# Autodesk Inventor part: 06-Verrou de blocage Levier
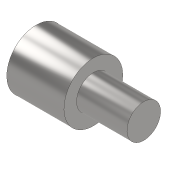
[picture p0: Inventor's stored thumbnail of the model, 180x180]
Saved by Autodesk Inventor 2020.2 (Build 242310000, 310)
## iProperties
Created: 2022-02
Part Number: 06-Verrou de blocage Levier
Material: Acier, alliage
Document SubType Name: Modeling
Designer: Philippe
Density: 7.73 g/cm^3
Appearance: Semi-poli
Author: Philippe
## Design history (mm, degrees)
derived "Base-Etau.ipt"
feature "06-Verrou de blocage Levier::Base-Etau.ipt" dims "d0" = 10
tag "FonctionRepérage1"
node "Solide1"
